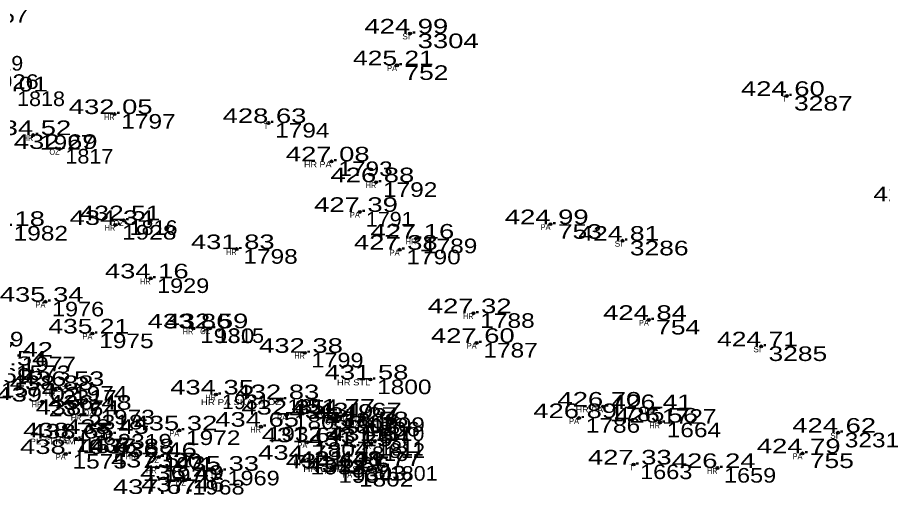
# Model space of a CAD drawing. Extents: x -639390 to -639074, y -1138747 to -1138358.
# Drawn here: x -639287.05 to -639242.68, y -1138541.18 to -1138517.05 of the extents above; entities that cross this region are included whole.
import ezdxf
from ezdxf.enums import TextEntityAlignment as Align

# ---------------------------------------------------------------- set-up
doc = ezdxf.new("R2010")
doc.units = 0
doc.header["$LTSCALE"] = 0.3
doc.header["$PDMODE"] = 32
doc.header["$PDSIZE"] = 0.15
for name, color, linetype in [('11', 7, 'Continuous'), ('12', 7, 'Continuous'), ('13', 7, 'Continuous'), ('57', 7, 'Continuous')]:
    doc.layers.add(name, color=color, linetype=linetype)

msp = doc.modelspace()

# ---------------------------------------------------------------- linework, layer by layer
at = {"layer": '11'}
for p in [(-639266.91, -1138517.88), (-639267.58, -1138519.51), (-639247.6, -1138521.08), (-639282.07, -1138522.01), (-639274.18, -1138522.47), (-639286.24, -1138523.09), (-639284.89, -1138523.8), (-639270.94, -1138524.44), (-639268.65, -1138525.51), (-639269.49, -1138527.03), (-639281.6, -1138527.46), (-639282.03, -1138527.7), (-639259.71, -1138527.66), (-639266.6, -1138528.4), (-639256.02, -1138528.51), (-639275.81, -1138528.94), (-639267.45, -1138528.97), (-639280.22, -1138530.44), (-639285.61, -1138531.64), (-639263.66, -1138532.23), (-639254.67, -1138532.57), (-639283.2, -1138533.27), (-639278.03, -1138533.01), (-639277.16, -1138533), (-639263.5, -1138533.75), (-639248.91, -1138533.93), (-639272.31, -1138534.26), (-639268.95, -1138535.63), (-639285.1, -1138536.17), (-639284.54, -1138535.96), (-639285.78, -1138536.76), (-639276.87, -1138536.4), (-639273.52, -1138536.64), (-639283.14, -1138537.18), (-639257.01, -1138537.02), (-639254.34, -1138537.15), (-639283.77, -1138537.44), (-639273.22, -1138537.43), (-639270.75, -1138537.64), (-639270.66, -1138537.38), (-639269.29, -1138537.57), (-639258.25, -1138537.61), (-639274.56, -1138538.05), (-639269.54, -1138537.8), (-639268.94, -1138538.03), (-639254.1, -1138537.84), (-639284.41, -1138538.6), (-639282.26, -1138538.42), (-639278.75, -1138538.24), (-639244.97, -1138538.36), (-639284.06, -1138538.66), (-639272.18, -1138538.85), (-639268.91, -1138538.9), (-639268.72, -1138538.78), (-639284.57, -1138539.45), (-639280.96, -1138539.42), (-639269.78, -1138539.06), (-639246.79, -1138539.42), (-639279.8, -1138539.61), (-639272.36, -1138539.75), (-639279.91, -1138540.14), (-639276.61, -1138540.31), (-639270.94, -1138540.18), (-639270.27, -1138540.06), (-639269.88, -1138540.37), (-639268.26, -1138540.07), (-639255.45, -1138539.99), (-639251.15, -1138540.17), (-639278.41, -1138540.78)]:
    msp.add_point(p, dxfattribs=at)

# ---------------------------------------------------------------- texts
at = {"layer": '12'}
for s, width, p in [('424.99 ', 1.4, (-639266.91, -1138517.88)), ('425.21 ', 1.35, (-639267.579, -1138519.51)), ('433.01 ', 1.35, (-639287.369, -1138520.85)), ('424.60 ', 1.4, (-639247.6, -1138521.08)), ('432.05 ', 1.4, (-639282.07, -1138522.01)), ('428.63 ', 1.4, (-639274.18, -1138522.47)), ('434.52 ', 1.4, (-639286.24, -1138523.09)), ('432.69 ', 1.4, (-639284.89, -1138523.8)), ('427.08 ', 1.4, (-639270.94, -1138524.44)), ('426.88 ', 1.4, (-639268.65, -1138525.51)), ('424.51 ', 1.35, (-639240.899, -1138526.49)), ('427.39 ', 1.4, (-639269.49, -1138527.03)), ('435.18 ', 1.4, (-639287.59, -1138527.75)), ('434.34 ', 1.4, (-639282.03, -1138527.7)), ('432.51 ', 1.35, (-639281.599, -1138527.46)), ('424.99 ', 1.4, (-639259.71, -1138527.66)), ('427.16 ', 1.4, (-639266.599, -1138528.4)), ('424.81 ', 1.35, (-639256.019, -1138528.51)), ('431.83 ', 1.4, (-639275.81, -1138528.94)), ('427.38 ', 1.4, (-639267.45, -1138528.97)), ('434.16 ', 1.4, (-639280.219, -1138530.44)), ('435.34 ', 1.4, (-639285.61, -1138531.64)), ('427.32 ', 1.4, (-639263.66, -1138532.23)), ('424.84 ', 1.4, (-639254.67, -1138532.57)), ('433.86 ', 1.4, (-639278.029, -1138533.01)), ('432.59 ', 1.4, (-639277.16, -1138533)), ('435.21 ', 1.35, (-639283.199, -1138533.27)), ('427.60 ', 1.4, (-639263.5, -1138533.75)), ('424.71 ', 1.35, (-639248.909, -1138533.93)), ('432.38 ', 1.4, (-639272.31, -1138534.26)), ('437.42 ', 1.4, (-639287.18, -1138534.46)), ('439.54 ', 1.4, (-639287.47, -1138534.91)), ('431.58 ', 1.4, (-639268.95, -1138535.63)), ('439.69 ', 1.4, (-639288.24, -1138535.79)), ('438.88 ', 1.4, (-639285.1, -1138536.17)), ('436.53 ', 1.4, (-639284.54, -1138535.96)), ('434.35 ', 1.4, (-639276.87, -1138536.4)), ('439.02 ', 1.4, (-639285.78, -1138536.76)), ('432.83 ', 1.4, (-639273.52, -1138536.64)), ('426.70 ', 1.4, (-639257.01, -1138537.02)), ('438.74 ', 1.4, (-639283.77, -1138537.44)), ('436.48 ', 1.4, (-639283.14, -1138537.18)), ('432.35 ', 1.4, (-639273.22, -1138537.43)), ('431.77 ', 1.4, (-639270.66, -1138537.38)), ('426.41 ', 1.35, (-639254.339, -1138537.15)), ('431.49 ', 1.4, (-639270.75, -1138537.64)), ('431.27 ', 1.4, (-639269.54, -1138537.8)), ('431.67 ', 1.4, (-639269.29, -1138537.57)), ('426.89 ', 1.4, (-639258.25, -1138537.61)), ('426.56 ', 1.4, (-639254.099, -1138537.84)), ('435.32 ', 1.4, (-639278.75, -1138538.24)), ('434.65 ', 1.4, (-639274.56, -1138538.05)), ('431.58 ', 1.4, (-639268.94, -1138538.03)), ('424.62 ', 1.4, (-639244.97, -1138538.36)), ('438.73 ', 1.4, (-639284.41, -1138538.6)), ('438.65 ', 1.4, (-639284.06, -1138538.66)), ('438.45 ', 1.4, (-639282.26, -1138538.42)), ('431.67 ', 1.4, (-639268.72, -1138538.78)), ('431.67 ', 1.4, (-639272.18, -1138538.85)), ('431.25 ', 1.4, (-639269.78, -1138539.06)), ('431.54 ', 1.4, (-639268.91, -1138538.9)), ('438.70 ', 1.4, (-639284.57, -1138539.45)), ('437.88 ', 1.4, (-639280.96, -1138539.42)), ('436.46 ', 1.4, (-639279.799, -1138539.61)), ('424.79 ', 1.4, (-639246.79, -1138539.42)), ('437.57 ', 1.4, (-639279.91, -1138540.14)), ('434.73 ', 1.4, (-639272.36, -1138539.75)), ('434.62 ', 1.4, (-639270.94, -1138540.18)), ('431.48 ', 1.4, (-639270.27, -1138540.06)), ('431.77 ', 1.4, (-639268.26, -1138540.07)), ('427.33 ', 1.4, (-639255.45, -1138539.99)), ('426.24 ', 1.4, (-639251.15, -1138540.17)), ('435.33 ', 1.4, (-639276.61, -1138540.31)), ('431.66 ', 1.4, (-639269.879, -1138540.37)), ('436.49 ', 1.4, (-639278.41, -1138540.78)), ('437.67 ', 1.4, (-639279.81, -1138541.5)), ('437.46 ', 1.4, (-639278.369, -1138541.38))]:
    msp.add_text(s, height=0.75, dxfattribs=dict(at, width=width)).set_placement(p, align=Align.CENTER)
at = {"layer": '13'}
for s, width, p in [(' 1857', 1.25, (-639289.62, -1138517.33)), (' 3304', 1.4, (-639266.91, -1138518.63)), (' 1819', 1.1, (-639289.51, -1138519.78)), (' 752', 1.35, (-639267.58, -1138520.26)), (' 1926', 1.2, (-639288.97, -1138520.72)), (' 1818', 1.1, (-639287.37, -1138521.6)), (' 3287', 1.35, (-639247.6, -1138521.83)), (' 1797', 1.25, (-639282.07, -1138522.76)), (' 1794', 1.25, (-639274.18, -1138523.22)), (' 1927', 1.25, (-639286.24, -1138523.84)), (' 1817', 1.1, (-639284.89, -1138524.55)), (' 1793', 1.25, (-639270.94, -1138525.19)), (' 1792', 1.25, (-639268.65, -1138526.26)), (' 1791', 1.1, (-639269.49, -1138527.78)), (' 1982', 1.25, (-639287.59, -1138528.5)), (' 1928', 1.25, (-639282.03, -1138528.45)), (' 1816', 1.1, (-639281.6, -1138528.21)), (' 753', 1.35, (-639259.71, -1138528.41)), (' 1789', 1.25, (-639266.6, -1138529.15)), (' 3286', 1.35, (-639256.02, -1138529.26)), (' 1798', 1.25, (-639275.81, -1138529.69)), (' 1790', 1.25, (-639267.45, -1138529.72)), (' 1929', 1.2, (-639280.22, -1138531.19)), (' 1976', 1.2, (-639285.61, -1138532.39)), (' 1788', 1.25, (-639263.66, -1138532.98)), (' 754', 1.35, (-639254.67, -1138533.32)), (' 1489', 1.25, (-639289.87, -1138533.93)), (' 1930', 1.25, (-639278.03, -1138533.76)), (' 1815', 1.1, (-639277.16, -1138533.75)), (' 1975', 1.25, (-639283.2, -1138534.02)), (' 1787', 1.25, (-639263.5, -1138534.5)), (' 3285', 1.35, (-639248.91, -1138534.68)), (' 1977', 1.25, (-639287.18, -1138535.21)), (' 1799', 1.2, (-639272.31, -1138535.01)), (' 1573', 1.25, (-639287.47, -1138535.66)), (' 1574', 1.25, (-639288.24, -1138536.54)), (' 1800', 1.25, (-639268.95, -1138536.38)), (' 2317', 1.25, (-639285.1, -1138536.92)), (' 1974', 1.25, (-639284.54, -1138536.71)), (' 2316', 1.25, (-639285.78, -1138537.51)), (' 1931', 1.1, (-639276.87, -1138537.15)), (' 1814', 1.15, (-639273.52, -1138537.39)), (' 1973', 1.25, (-639283.14, -1138537.93)), (' 1785', 1.25, (-639257.01, -1138537.77)), (' 1727', 1.25, (-639254.34, -1138537.9)), (' 2318', 1.25, (-639283.77, -1138538.19)), (' 1805', 1.25, (-639273.22, -1138538.18)), (' 1807', 1.25, (-639270.75, -1138538.39)), (' 1808', 1.25, (-639270.66, -1138538.13)), (' 1809', 1.25, (-639269.29, -1138538.32)), (' 1786', 1.25, (-639258.25, -1138538.36)), (' 1932', 1.25, (-639274.56, -1138538.8)), (' 1806', 1.25, (-639269.54, -1138538.55)), (' 1810', 1.1, (-639268.94, -1138538.78)), (' 1664', 1.25, (-639254.1, -1138538.59)), (' 2319', 1.25, (-639282.26, -1138539.17)), (' 1972', 1.25, (-639278.75, -1138538.99)), (' 3231', 1.25, (-639244.97, -1138539.11)), (' 1488', 1.25, (-639284.41, -1138539.35)), (' 1576', 1.25, (-639284.06, -1138539.41)), (' 1804', 1.25, (-639272.18, -1138539.6)), (' 1812', 1.1, (-639268.91, -1138539.65)), (' 2320', 1.35, (-639280.96, -1138540.17)), (' 1813', 1.1, (-639269.78, -1138539.81)), (' 1575', 1.25, (-639284.57, -1138540.2)), (' 1971', 1.1, (-639279.8, -1138540.36)), (' 1933', 1.25, (-639272.36, -1138540.5)), (' 755', 1.35, (-639246.79, -1138540.17)), (' 1970', 1.25, (-639279.91, -1138540.89)), (' 1969', 1.2, (-639276.61, -1138541.06)), (' 1934', 1.25, (-639270.94, -1138540.93)), (' 1803', 1.25, (-639270.27, -1138540.81)), (' 1801', 1.1, (-639268.26, -1138540.82)), (' 1663', 1.2, (-639255.45, -1138540.74)), (' 1659', 1.2, (-639251.15, -1138540.92)), (' 1802', 1.25, (-639269.88, -1138541.12)), (' 1968', 1.2, (-639278.41, -1138541.53))]:
    msp.add_text(s, height=0.75, dxfattribs=dict(at, width=width)).set_placement(p)
msp.add_text(' 1811', height=0.75, dxfattribs=at).set_placement((-639268.72, -1138539.53))
at = {"layer": '57'}
for s, width, p in [('SI', 1.05, (-639266.91, -1138518.18)), ('PA', 0.95, (-639267.58, -1138519.81)), ('T', 0.85, (-639247.6, -1138521.38)), ('HR', 0.85, (-639282.069, -1138522.31)), ('T', 0.85, (-639274.18, -1138522.77)), ('HR', 0.85, (-639286.239, -1138523.39)), ('OZ', 0.9, (-639284.889, -1138524.1)), ('HR PA', 1.15, (-639270.94, -1138524.74)), ('HR', 0.85, (-639268.649, -1138525.81)), ('PA', 0.95, (-639269.49, -1138527.33)), ('HR', 0.85, (-639282.029, -1138528)), ('OZ', 0.9, (-639281.599, -1138527.76)), ('PA', 0.95, (-639259.71, -1138527.96)), ('HR', 0.85, (-639266.599, -1138528.7)), ('SI', 1.05, (-639256.02, -1138528.81)), ('HR', 0.85, (-639275.809, -1138529.24)), ('PA', 0.95, (-639267.45, -1138529.27)), ('HR', 0.85, (-639280.219, -1138530.74)), ('PA', 0.95, (-639285.61, -1138531.94)), ('HR', 0.85, (-639263.659, -1138532.53)), ('PA', 0.95, (-639254.67, -1138532.87)), ('HR', 0.85, (-639278.029, -1138533.31)), ('OZ', 0.9, (-639277.159, -1138533.3)), ('PA', 0.95, (-639283.2, -1138533.57)), ('PA', 0.95, (-639263.5, -1138534.05)), ('SI', 1.05, (-639248.91, -1138534.23)), ('HR', 0.85, (-639272.309, -1138534.56)), ('HR STL', 1.2, (-639268.949, -1138535.93)), ('HR', 0.85, (-639285.099, -1138536.47)), ('OZ', 0.9, (-639284.539, -1138536.26)), ('HR PA SKALA OZ', 1.25, (-639273.519, -1138536.94)), ('HR', 0.85, (-639276.869, -1138536.7)), ('HR', 0.85, (-639285.779, -1138537.06)), ('OZ', 0.9, (-639283.139, -1138537.48)), ('HR PA', 1.15, (-639257.01, -1138537.32)), ('HR', 0.85, (-639254.339, -1138537.45)), ('HR', 0.85, (-639283.769, -1138537.74)), ('PA', 0.95, (-639273.22, -1138537.73)), ('OZ K', 1.15, (-639270.659, -1138537.68)), ('OZ', 0.9, (-639270.749, -1138537.94)), ('K HR', 1.15, (-639269.289, -1138537.87)), ('PA', 0.95, (-639258.25, -1138537.91)), ('HR', 0.85, (-639274.559, -1138538.35)), ('OZ', 0.9, (-639269.539, -1138538.1)), ('K', 0.65, (-639268.939, -1138538.33)), ('HR', 0.85, (-639254.099, -1138538.14)), ('HR', 0.85, (-639282.259, -1138538.72)), ('PA', 0.95, (-639278.75, -1138538.54)), ('SI', 1.05, (-639244.97, -1138538.66)), ('PL SLKAM', 1.2, (-639284.06, -1138538.96)), ('CE', 0.9, (-639284.41, -1138538.9)), ('PA', 0.95, (-639272.18, -1138539.15)), ('K', 0.65, (-639268.909, -1138539.2)), ('K', 0.65, (-639268.719, -1138539.08)), ('T', 0.85, (-639269.78, -1138539.36)), ('PA', 0.95, (-639284.57, -1138539.75)), ('HR', 0.85, (-639280.959, -1138539.72)), ('OZ', 0.9, (-639279.799, -1138539.91)), ('HR', 0.85, (-639272.359, -1138540.05)), ('PA', 0.95, (-639246.79, -1138539.72)), ('HR', 0.85, (-639279.909, -1138540.44)), ('HR OZ PA SKALA', 1.25, (-639268.26, -1138540.37)), ('HR', 0.85, (-639270.939, -1138540.48)), ('PA', 0.95, (-639270.27, -1138540.36)), ('T', 0.85, (-639255.45, -1138540.29)), ('HR', 0.85, (-639251.149, -1138540.47)), ('PA', 0.95, (-639276.61, -1138540.61)), ('PA', 0.95, (-639269.88, -1138540.67)), ('OZ', 0.9, (-639278.409, -1138541.08))]:
    msp.add_text(s, height=0.3, dxfattribs=dict(at, width=width)).set_placement(p, align=Align.RIGHT)

doc.saveas('drawing.dxf')
